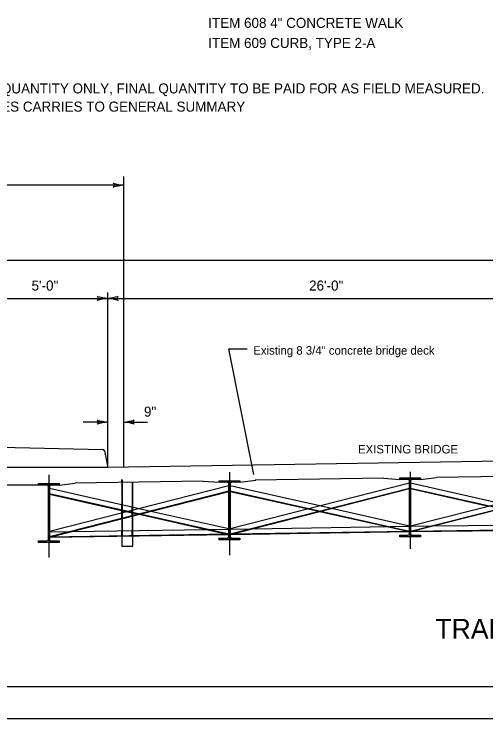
# Model space of a CAD drawing. Extents: x -706 to 14950, y -1867 to 6417.
# Drawn here: x -405 to -185.1, y -336.5 to -7.9 of the extents above; entities that cross this region are included whole.
import ezdxf

# ---------------------------------------------------------------- set-up
doc = ezdxf.new("R2010")
doc.units = 0
for name, color, linetype in [('Level 1', 7, 'Continuous'), ('Level 43', 7, 'Continuous'), ('Level 44', 7, 'Continuous'), ('Level 47', 7, 'Continuous'), ('Level 48', 7, 'Continuous')]:
    doc.layers.add(name, color=color, linetype=linetype)

msp = doc.modelspace()

# ---------------------------------------------------------------- linework, layer by layer
at = {"layer": 'Level 1'}
for p, q in [((-358.76, -86.76), (-358.77, -86.76)), ((-366.26, -139.49), (-366.27, -139.49)), ((-356.49, -141.34), (-356.49, -141.34)), ((-366.26, -197.16), (-366.27, -197.16)), ((-348.99, -199.01), (-348.99, -199.01))]:
    msp.add_line(p, q, dxfattribs=at)
for points in [[(-574.95, 323.53), (445.05, 323.53), (445.05, -336.47), (-574.95, -336.47)], [(-514.95, 308.53), (430.05, 308.53), (430.05, -321.47), (-514.95, -321.47)]]:
    msp.add_lwpolyline(points, close=True, dxfattribs=at)
for centre, start, end in [((-349.48, -51.15), 255.3829, 263.1374), ((-349.48, -124.23), 96.8626, 104.6171), ((-356.98, -103.87), 255.3829, 263.1374), ((-356.98, -176.95), 96.8626, 104.6171), ((-365.77, -103.87), 276.8626, 284.6171), ((-365.77, -176.95), 75.3829, 83.1374), ((-356.98, -161.55), 255.3829, 263.1374), ((-356.98, -234.62), 96.8626, 104.6171), ((-358.27, -161.55), 276.8626, 284.6171), ((-358.27, -234.62), 75.3829, 83.1374)]:
    msp.add_arc(centre, 36.8, start, end, dxfattribs=at)
for centre, major_axis in [((-359.41, -87.69), (1.25, 0)), ((-366.91, -140.41), (1.25, 0)), ((-355.84, -140.42), (-1.25, 0)), ((-366.91, -198.08), (1.25, 0)), ((-348.34, -198.09), (-1.25, 0))]:
    msp.add_ellipse(centre, major_axis=major_axis, ratio=0.873734, start_param=5.258637, end_param=7.300638, dxfattribs=at)
at = {"layer": 'Level 43'}
for p, q in [((-411.38, -209.85), (-363.71, -210.88)), ((-362.91, -211.55), (-361.38, -219.23)), ((-136.27, -215.71), (-361.38, -219.22)), ((-361.38, -219.23), (-421.38, -219.23)), ((-148.57, -222.98), (-208.15, -223.91)), ((-383.98, -227.47), (-376.48, -226.54)), ((-316.9, -225.61), (-376.48, -226.54)), ((-354.71, -226.2), (-354.71, -224.9)), ((-354.71, -226.2), (-354.71, -236.71)), ((-354.4, -226.2), (-354.4, -224.98)), ((-354.4, -236.78), (-354.4, -226.2)), ((-350.03, -226.13), (-350.03, -237.76)), ((-349.71, -237.83), (-349.71, -226.13)), ((-316.9, -225.61), (-309.4, -226.15)), ((-309.4, -226.15), (-309.4, -225.42)), ((-309.4, -225.42), (-299.81, -225.42)), ((-309.4, -226.04), (-308.78, -225.42)), ((-305.68, -226.15), (-309.4, -226.15)), ((-308.94, -226.15), (-308.21, -225.42)), ((-307.67, -226.15), (-306.94, -225.42)), ((-307.1, -226.15), (-306.37, -225.42)), ((-305.83, -226.15), (-305.1, -225.42)), ((-305.68, -226.15), (-305.68, -226.15)), ((-305.36, -226.24), (-304.54, -225.42)), ((-304.85, -227.01), (-303.26, -225.42)), ((-220.68, -226.5), (-304.36, -247.86)), ((-299.81, -226.15), (-303.53, -226.15)), ((-303.43, -226.15), (-302.7, -225.42)), ((-302.15, -226.15), (-301.42, -225.42)), ((-301.59, -226.15), (-300.86, -225.42)), ((-300.31, -226.15), (-299.81, -225.65)), ((-299.81, -226.15), (-292.32, -225.23)), ((-299.81, -225.42), (-299.81, -226.15)), ((-232.73, -224.3), (-292.62, -225.23)), ((-232.73, -224.3), (-225.23, -224.84)), ((-225.23, -224.84), (-225.23, -224.11)), ((-225.23, -224.11), (-215.65, -224.11)), ((-225.23, -224.73), (-224.61, -224.11)), ((-221.51, -224.84), (-225.23, -224.84)), ((-224.77, -224.84), (-224.05, -224.11)), ((-223.5, -224.84), (-222.77, -224.11)), ((-222.94, -224.84), (-222.21, -224.11)), ((-221.66, -224.84), (-220.93, -224.11)), ((-221.51, -224.84), (-221.51, -224.84)), ((-221.19, -224.93), (-220.37, -224.11)), ((-220.68, -225.69), (-219.1, -224.11)), ((-220.68, -250.04), (-220.68, -225.67)), ((-220.68, -226.26), (-220.2, -225.77)), ((-136.51, -225.35), (-220.2, -246.54)), ((-220.2, -225.67), (-220.2, -250.04)), ((-178.44, -235.97), (-220.2, -226.5)), ((-215.65, -224.84), (-219.36, -224.84)), ((-219.26, -224.84), (-218.53, -224.11)), ((-217.99, -224.84), (-217.26, -224.11)), ((-217.42, -224.84), (-216.69, -224.11)), ((-216.15, -224.84), (-215.65, -224.34)), ((-215.65, -224.84), (-208.15, -223.91)), ((-215.65, -224.11), (-215.65, -224.84)), ((-393.56, -227.47), (-418.46, -227.47)), ((-393.56, -227.47), (-393.56, -226.74)), ((-393.56, -226.74), (-383.98, -226.74)), ((-393.56, -227.36), (-392.94, -226.74)), ((-389.85, -227.47), (-393.56, -227.47)), ((-393.11, -227.47), (-392.38, -226.74)), ((-391.83, -227.47), (-391.11, -226.74)), ((-391.27, -227.47), (-390.54, -226.74)), ((-390, -227.47), (-389.27, -226.74)), ((-389.85, -227.47), (-389.85, -227.47)), ((-389.52, -227.56), (-388.7, -226.74)), ((-389.01, -228.32), (-387.43, -226.74)), ((-389.01, -252.67), (-389.01, -228.3)), ((-389.01, -228.89), (-388.53, -228.4)), ((-389.01, -230.16), (-388.53, -229.68)), ((-304.85, -227.82), (-388.53, -249.17)), ((-388.53, -228.3), (-388.53, -252.67)), ((-346.71, -238.5), (-388.53, -229.13)), ((-383.98, -227.47), (-387.7, -227.47)), ((-387.59, -227.47), (-386.86, -226.74)), ((-386.32, -227.47), (-385.59, -226.74)), ((-385.75, -227.47), (-385.02, -226.74)), ((-384.48, -227.47), (-383.98, -226.97)), ((-383.98, -226.74), (-383.98, -227.47)), ((-304.85, -251.36), (-304.85, -226.98)), ((-304.85, -227.57), (-304.36, -227.09)), ((-304.85, -228.85), (-304.36, -228.36)), ((-304.85, -229.41), (-304.36, -228.93)), ((-304.36, -226.98), (-304.36, -251.36)), ((-262.54, -237.19), (-304.36, -227.82)), ((-304.36, -250.19), (-220.68, -228.84)), ((-304.36, -250.46), (-220.68, -229.1)), ((-220.68, -227.53), (-220.2, -227.05)), ((-220.68, -228.1), (-220.2, -227.61)), ((-220.68, -229.37), (-220.2, -228.89)), ((-220.68, -229.93), (-220.2, -229.45)), ((-220.2, -248.87), (-136.58, -227.69)), ((-220.2, -249.14), (-136.51, -227.95)), ((-220.2, -228.82), (-136.51, -247.79)), ((-220.2, -229.09), (-183.82, -237.33)), ((-389.01, -230.73), (-388.53, -230.24)), ((-389.01, -232), (-388.53, -231.52)), ((-389.01, -232.56), (-388.53, -232.08)), ((-388.53, -251.5), (-304.85, -230.15)), ((-388.53, -251.77), (-304.85, -230.42)), ((-388.53, -231.45), (-304.85, -250.19)), ((-388.53, -231.71), (-352.09, -239.87)), ((-304.85, -230.68), (-304.36, -230.2)), ((-304.85, -231.25), (-304.36, -230.77)), ((-304.85, -232.52), (-304.36, -232.04)), ((-304.85, -233.09), (-304.36, -232.6)), ((-304.36, -230.13), (-220.68, -248.88)), ((-304.36, -230.4), (-267.93, -238.56)), ((-220.68, -231.21), (-220.2, -230.72)), ((-220.68, -231.77), (-220.2, -231.29)), ((-220.68, -233.05), (-220.2, -232.56)), ((-220.68, -233.61), (-220.2, -233.13)), ((-389.01, -233.84), (-388.53, -233.35)), ((-389.01, -234.4), (-388.53, -233.92)), ((-389.01, -235.68), (-388.53, -235.19)), ((-389.01, -236.24), (-388.53, -235.76)), ((-304.85, -234.36), (-304.36, -233.88)), ((-304.85, -234.93), (-304.36, -234.44)), ((-304.85, -236.2), (-304.36, -235.72)), ((-304.85, -236.76), (-304.36, -236.28)), ((-220.68, -234.88), (-220.2, -234.4)), ((-220.68, -235.45), (-220.2, -234.97)), ((-220.68, -236.72), (-220.2, -236.24)), ((-389.01, -237.51), (-388.53, -237.03)), ((-389.01, -238.08), (-388.53, -237.6)), ((-389.01, -239.35), (-388.53, -238.87)), ((-389.01, -239.92), (-388.53, -239.43)), ((-354.71, -239.29), (-354.71, -236.71)), ((-354.71, -240.54), (-354.71, -239.29)), ((-354.4, -239.36), (-354.4, -236.78)), ((-354.4, -239.36), (-354.4, -240.46)), ((-350.03, -241.95), (-350.03, -237.76)), ((-349.71, -241.87), (-349.71, -237.83)), ((-341.28, -239.72), (-346.71, -238.5)), ((-304.85, -247.88), (-341.28, -239.72)), ((-304.85, -238.04), (-304.36, -237.55)), ((-304.85, -238.6), (-304.36, -238.12)), ((-304.85, -239.88), (-304.36, -239.39)), ((-267.93, -238.56), (-262.5, -239.78)), ((-257.12, -238.4), (-262.54, -237.19)), ((-262.5, -239.78), (-231.13, -246.8)), ((-220.68, -246.56), (-257.12, -238.4)), ((-220.68, -237.29), (-220.2, -236.8)), ((-220.68, -238.56), (-220.2, -238.08)), ((-220.68, -239.13), (-220.2, -238.64)), ((-389.01, -241.19), (-388.53, -240.71)), ((-389.01, -241.76), (-388.53, -241.27)), ((-389.01, -243.03), (-388.53, -242.55)), ((-389.01, -243.6), (-388.53, -243.11)), ((-354.71, -243.14), (-354.71, -240.54)), ((-354.71, -243.14), (-354.71, -248.74)), ((-354.4, -243.06), (-354.4, -240.46)), ((-354.4, -248.74), (-354.4, -243.06)), ((-352.09, -239.87), (-346.67, -241.09)), ((-350.03, -241.95), (-350.03, -248.67)), ((-349.71, -248.66), (-349.71, -241.87)), ((-346.67, -241.09), (-315.29, -248.12)), ((-304.85, -240.44), (-304.36, -239.96)), ((-304.85, -241.71), (-304.36, -241.23)), ((-304.85, -242.28), (-304.36, -241.8)), ((-304.85, -243.55), (-304.36, -243.07)), ((-220.68, -240.4), (-220.2, -239.92)), ((-220.68, -240.97), (-220.2, -240.48)), ((-220.68, -242.24), (-220.2, -241.75)), ((-220.68, -242.8), (-220.2, -242.32)), ((-389.01, -244.87), (-388.53, -244.38)), ((-389.01, -245.43), (-388.53, -244.95)), ((-389.01, -246.71), (-388.53, -246.22)), ((-304.85, -244.12), (-304.36, -243.64)), ((-304.85, -245.39), (-304.36, -244.91)), ((-304.85, -245.96), (-304.36, -245.47)), ((-220.68, -244.08), (-220.2, -243.59)), ((-220.68, -244.64), (-220.2, -244.16)), ((-220.68, -245.91), (-220.2, -245.43)), ((-220.68, -246.48), (-220.2, -246)), ((-209.79, -246.51), (-136.51, -245.56)), ((-389.01, -247.27), (-388.53, -246.79)), ((-389.01, -248.54), (-388.53, -248.06)), ((-389.01, -249.11), (-388.53, -248.63)), ((-388.53, -249.27), (-378.09, -249.11)), ((-377.98, -249.11), (-304.85, -247.96)), ((-354.71, -251.24), (-354.71, -248.74)), ((-354.4, -251.24), (-354.4, -248.74)), ((-350.03, -251.17), (-350.03, -248.67)), ((-349.71, -251.16), (-349.71, -248.66)), ((-315.28, -248.12), (-304.85, -250.46)), ((-304.85, -247.23), (-304.36, -246.75)), ((-304.85, -247.8), (-304.36, -247.31)), ((-304.85, -249.07), (-304.36, -248.58)), ((-304.85, -249.63), (-304.36, -249.15)), ((-304.36, -247.96), (-293.92, -247.79)), ((-304.36, -250.2), (-220.68, -248.88)), ((-304.36, -250.46), (-220.68, -249.14)), ((-293.82, -247.79), (-220.68, -246.64)), ((-231.11, -246.81), (-220.68, -249.14)), ((-220.7, -250.17), (-220.2, -249.67)), ((-220.68, -247.75), (-220.2, -247.27)), ((-220.68, -248.32), (-220.2, -247.84)), ((-220.68, -249.59), (-220.2, -249.11)), ((-220.2, -246.64), (-209.79, -246.51)), ((-220.2, -248.88), (-136.51, -247.8)), ((-220.2, -249.14), (-136.51, -248.06)), ((-389.03, -252.8), (-388.53, -252.3)), ((-389.01, -250.38), (-388.53, -249.9)), ((-389.01, -250.95), (-388.53, -250.47)), ((-389.01, -252.22), (-388.53, -251.74)), ((-388.53, -251.51), (-304.85, -250.2)), ((-388.53, -251.77), (-304.85, -250.46)), ((-354.71, -251.24), (-354.71, -255.9)), ((-349.71, -255.9), (-349.71, -251.16)), ((-309.4, -252.92), (-309.4, -252.12)), ((-309.4, -252.19), (-305.68, -252.19)), ((-309.4, -252.35), (-309.24, -252.19)), ((-299.81, -252.92), (-309.4, -252.92)), ((-308.7, -252.92), (-307.97, -252.19)), ((-308.14, -252.92), (-307.41, -252.19)), ((-306.86, -252.92), (-306.13, -252.19)), ((-306.3, -252.92), (-305.53, -252.16)), ((-305.02, -252.92), (-304.07, -251.97)), ((-304.86, -251.49), (-304.36, -250.99)), ((-304.85, -250.91), (-304.36, -250.42)), ((-304.46, -252.92), (-303.7, -252.16)), ((-303.53, -252.19), (-299.81, -252.19)), ((-303.19, -252.92), (-302.46, -252.19)), ((-302.62, -252.92), (-301.89, -252.19)), ((-301.35, -252.92), (-300.62, -252.19)), ((-300.78, -252.92), (-300.05, -252.19)), ((-299.81, -252.19), (-299.81, -252.92)), ((-225.23, -251.61), (-225.23, -250.81)), ((-225.23, -250.88), (-221.51, -250.88)), ((-225.23, -251.03), (-225.08, -250.88)), ((-215.65, -251.61), (-225.23, -251.61)), ((-224.53, -251.61), (-223.81, -250.88)), ((-223.97, -251.61), (-223.24, -250.88)), ((-222.7, -251.61), (-221.97, -250.88)), ((-222.13, -251.61), (-221.36, -250.84)), ((-220.86, -251.61), (-219.9, -250.65)), ((-220.29, -251.61), (-219.53, -250.85)), ((-219.36, -250.88), (-215.65, -250.88)), ((-219.02, -251.61), (-218.29, -250.88)), ((-218.45, -251.61), (-217.72, -250.88)), ((-217.18, -251.61), (-216.45, -250.88)), ((-216.61, -251.61), (-215.89, -250.88)), ((-215.65, -250.88), (-215.65, -251.61)), ((-393.56, -254.24), (-393.56, -253.44)), ((-393.56, -253.51), (-389.85, -253.51)), ((-393.56, -253.66), (-393.41, -253.51)), ((-383.98, -254.24), (-393.56, -254.24)), ((-392.87, -254.24), (-392.14, -253.51)), ((-392.3, -254.24), (-391.57, -253.51)), ((-391.03, -254.24), (-390.3, -253.51)), ((-390.46, -254.24), (-389.7, -253.47)), ((-389.19, -254.24), (-388.24, -253.28)), ((-388.62, -254.24), (-387.86, -253.48)), ((-387.7, -253.51), (-383.98, -253.51)), ((-387.35, -254.24), (-386.62, -253.51)), ((-386.79, -254.24), (-386.06, -253.51)), ((-385.51, -254.24), (-384.78, -253.51)), ((-384.95, -254.24), (-384.22, -253.51)), ((-383.98, -253.51), (-383.98, -254.24)), ((-354.71, -255.9), (-349.71, -255.9))]:
    msp.add_line(p, q, dxfattribs=at)
for centre, start, end in [((-363.73, -211.71), 11.3099, 88.7673), ((-305.68, -226.98), 0, 90), ((-303.53, -226.98), 90, 180), ((-221.51, -225.67), 0, 90), ((-219.36, -225.67), 90, 180), ((-389.85, -228.3), 0, 90), ((-387.7, -228.3), 90, 180), ((-389.85, -252.67), 270, 0), ((-387.7, -252.67), 180, 270), ((-305.68, -251.36), 270, 0), ((-303.53, -251.36), 180, 270), ((-221.51, -250.04), 270, 0), ((-219.36, -250.04), 180, 270)]:
    msp.add_arc(centre, 0.833, start, end, dxfattribs=at)
at = {"layer": 'Level 47'}
for p, q in [((-353.88, -219.23), (-353.88, -83.6)), ((-353.88, -87.69), (-456.42, -87.69)), ((-421.38, -122.58), (148.83, -122.58)), ((-361.38, -219.23), (-361.38, -137.69)), ((-411.38, -140.41), (-361.38, -140.41)), ((-361.38, -140.41), (-136.27, -140.41)), ((-293.3, -222.55), (-304.89, -163.99)), ((-304.89, -163.99), (-296.42, -163.99)), ((-361.38, -198.08), (-372.8, -198.08)), ((-353.88, -198.08), (-342.83, -198.08))]:
    msp.add_line(p, q, dxfattribs=at)
at = {"layer": 'Level 48'}
for p, q in [((-388.77, -222.66), (-388.77, -261.25)), ((-304.61, -221.49), (-304.61, -260.09)), ((-220.44, -221.27), (-220.44, -257.16))]:
    msp.add_line(p, q, dxfattribs=at)

# ---------------------------------------------------------------- texts
at = {"layer": 'Level 44'}
for s, height, p in [('5\'-0"', 4.68, (-396.86, -136.78)), ('26\'-0"', 4.68, (-267.5, -136.78)), ('Existing 8 3/4" concrete bridge deck', 3.9688, (-293.52, -166.67)), ('9"', 4.68, (-344.45, -195.59)), ('EXISTING BRIDGE', 3.9688, (-244.69, -212.71)), ('TRANSVERSE SECTION', 9.2604, (-208.62, -299.09))]:
    msp.add_text(s, height=height, dxfattribs=at).set_placement(p)
at = {"layer": 'Level 47'}
for s, p in [('ITEM 608 4" CONCRETE WALK                                                     (5\' X 25\') X 4 = 500 SQ FT **', (-314.5, -14.32)), ('ITEM 609 CURB, TYPE 2-A                                                                      =  25 FT', (-314.5, -23.68)), ('** ESTIMATED QUANTITY ONLY, FINAL QUANTITY TO BE PAID FOR AS FIELD MEASURED.', (-455.28, -44.87)), ('QUANTITIES CARRIES TO GENERAL SUMMARY', (-440.21, -53.35))]:
    msp.add_text(s, height=4.68, dxfattribs=at).set_placement(p)

doc.saveas('drawing.dxf')
